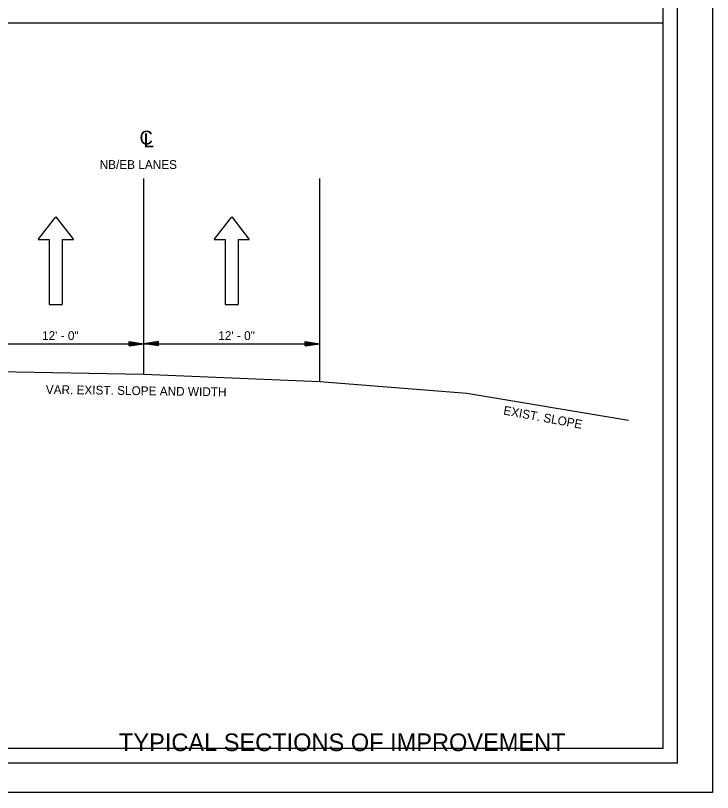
# Model space of a CAD drawing. Extents: x 1373889 to 1374222, y 382002 to 382215.
# Drawn here: x 1374127 to 1374221.8, y 382001.7 to 382107.4 of the extents above; entities that cross this region are included whole.
import ezdxf

# ---------------------------------------------------------------- set-up
doc = ezdxf.new("R2010")
doc.units = 0
for name, color, linetype in [('R_Border', 7, 'Continuous'), ('R_Border Title', 7, 'Continuous'), ('R_Draft', 7, 'Continuous'), ('R_No Plot', 7, 'Continuous'), ('R_Striping', 7, 'Continuous')]:
    doc.layers.add(name, color=color, linetype=linetype)

msp = doc.modelspace()

# ---------------------------------------------------------------- linework, layer by layer
at = {"layer": 'R_Border'}
for q in [(1374217.09, 382211.12), (1373900.91, 382005.66)]:
    msp.add_line((1374217.09, 382005.66), q, dxfattribs=at)
at = {"layer": 'R_Draft'}
for p, q in [((1374144.41, 382058.57), (1374144.41, 382085.23)), ((1374168.39, 382057.61), (1374168.39, 382085.23)), ((1374120.43, 382062.73), (1374144.41, 382062.73)), ((1374142.41, 382063.03), (1374144.41, 382062.73)), ((1374142.41, 382062.43), (1374142.41, 382063.03)), ((1374142.41, 382062.98), (1374144.07, 382062.73)), ((1374142.41, 382062.93), (1374143.73, 382062.73)), ((1374142.41, 382062.88), (1374143.4, 382062.73)), ((1374142.41, 382062.83), (1374143.06, 382062.73)), ((1374142.41, 382062.77), (1374142.72, 382062.73)), ((1374142.41, 382062.43), (1374144.41, 382062.73)), ((1374142.41, 382062.63), (1374143.06, 382062.73)), ((1374142.41, 382062.53), (1374143.73, 382062.73)), ((1374142.41, 382062.48), (1374144.07, 382062.73)), ((1374142.41, 382062.58), (1374143.4, 382062.73)), ((1374142.41, 382062.68), (1374142.72, 382062.73)), ((1374146.41, 382063.03), (1374144.41, 382062.73)), ((1374144.41, 382062.73), (1374168.39, 382062.73)), ((1374146.41, 382062.43), (1374144.41, 382062.73)), ((1374146.41, 382062.98), (1374144.74, 382062.73)), ((1374146.41, 382062.48), (1374144.74, 382062.73)), ((1374146.41, 382062.93), (1374145.08, 382062.73)), ((1374146.41, 382062.53), (1374145.08, 382062.73)), ((1374146.41, 382062.88), (1374145.42, 382062.73)), ((1374146.41, 382062.58), (1374145.42, 382062.73)), ((1374146.41, 382062.83), (1374145.76, 382062.73)), ((1374146.41, 382062.63), (1374145.76, 382062.73)), ((1374146.41, 382062.77), (1374146.09, 382062.73)), ((1374146.41, 382062.68), (1374146.09, 382062.73)), ((1374146.41, 382062.43), (1374146.41, 382063.03)), ((1374166.39, 382063.03), (1374168.39, 382062.73)), ((1374166.39, 382062.43), (1374166.39, 382063.03)), ((1374166.39, 382062.98), (1374168.05, 382062.73)), ((1374166.39, 382062.93), (1374167.71, 382062.73)), ((1374166.39, 382062.88), (1374167.38, 382062.73)), ((1374166.39, 382062.83), (1374167.04, 382062.73)), ((1374166.39, 382062.77), (1374166.7, 382062.73)), ((1374166.39, 382062.43), (1374168.39, 382062.73)), ((1374166.39, 382062.63), (1374167.04, 382062.73)), ((1374166.39, 382062.53), (1374167.71, 382062.73)), ((1374166.39, 382062.48), (1374168.05, 382062.73)), ((1374166.39, 382062.58), (1374167.38, 382062.73)), ((1374166.39, 382062.68), (1374166.7, 382062.73)), ((1374120.44, 382059.04), (1374144.41, 382058.57)), ((1374144.41, 382058.57), (1374168.39, 382057.61)), ((1374168.39, 382057.61), (1374188.41, 382056)), ((1374188.41, 382056), (1374210.41, 382052.33))]:
    msp.add_line(p, q, dxfattribs=at)
at = {"layer": 'R_No Plot'}
for points in [[(1373888.51, 382215.01), (1374221.85, 382215.01), (1374221.85, 382001.67), (1373888.51, 382001.67)], [(1373902.91, 382209.12), (1374152.45, 382209.12), (1374152.45, 382199.24), (1374169.99, 382199.24), (1374194.09, 382199.24), (1374194.09, 382176.9), (1374215.09, 382176.9), (1374215.09, 382007.66), (1373902.91, 382007.66)], [(1373902.91, 382106.39), (1374215.09, 382106.39), (1374215.09, 382007.66), (1373902.91, 382007.66)]]:
    msp.add_lwpolyline(points, close=True, dxfattribs=at)
at = {"layer": 'R_Striping'}
for p, q in [((1374130.03, 382076.89), (1374132.43, 382080.01)), ((1374132.43, 382080.01), (1374134.83, 382076.89)), ((1374153.99, 382076.89), (1374156.39, 382080.01)), ((1374156.39, 382080.01), (1374158.79, 382076.89)), ((1374130.03, 382076.89), (1374131.53, 382076.89)), ((1374131.53, 382076.89), (1374131.53, 382068.07)), ((1374133.33, 382076.89), (1374133.33, 382068.07)), ((1374133.33, 382076.89), (1374134.83, 382076.89)), ((1374153.99, 382076.89), (1374155.49, 382076.89)), ((1374155.49, 382076.89), (1374155.49, 382068.07)), ((1374157.29, 382076.89), (1374157.29, 382068.07)), ((1374157.29, 382076.89), (1374158.79, 382076.89)), ((1374131.53, 382068.07), (1374133.33, 382068.07)), ((1374155.49, 382068.07), (1374157.29, 382068.07))]:
    msp.add_line(p, q, dxfattribs=at)

# ---------------------------------------------------------------- texts
at = {"layer": 'R_Border Title'}
msp.add_text('TYPICAL SECTIONS OF IMPROVEMENT', height=2.4, dxfattribs=at).set_placement((1374141.04, 382007.3))
at = {"layer": 'R_Draft'}
for s, height, p in [('C', 1.88, (1374143.84, 382089.83)), ('L', 1.88, (1374144.4, 382089.46)), ('NB/EB LANES', 1.2, (1374138.41, 382086.51)), ('12\' - 0"', 1.2, (1374130.57, 382063.23)), ('12\' - 0"', 1.2, (1374154.56, 382063.23))]:
    msp.add_text(s, height=height, dxfattribs=at).set_placement(p)
for s, rotation, p in [('VAR. EXIST. SLOPE AND WIDTH', 359.2021, (1374131.07, 382055.91)), ('EXIST. SLOPE', 349.5661, (1374193.31, 382053.11))]:
    msp.add_text(s, height=1.2, rotation=rotation, dxfattribs=at).set_placement(p)

doc.saveas('drawing.dxf')
